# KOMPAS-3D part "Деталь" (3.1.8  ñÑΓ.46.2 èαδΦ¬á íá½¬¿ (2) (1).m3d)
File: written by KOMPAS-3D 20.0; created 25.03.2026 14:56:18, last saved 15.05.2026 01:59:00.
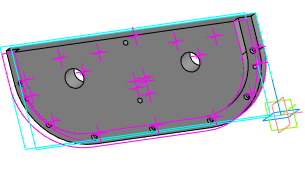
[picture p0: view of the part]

Document properties: Автор: TMK; Полное имя файла: E:\test_kompas\all_v18\3.1.8  дет.46.2 Крышка балки (2) (1).m3d; Организация: TMK

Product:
- Part/product: Деталь
    Масса: 21.9342
  - Body: Тело 3
  - Body: Тело 1

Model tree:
1. Операция без истории:1
2. Эскиз:1
3. Смещенная плоскость:1  (with: Операция без истории:1)
4. Эскиз:2
5. Смещенная плоскость:2  (with: Операция без истории:1)
6. Эскиз:3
